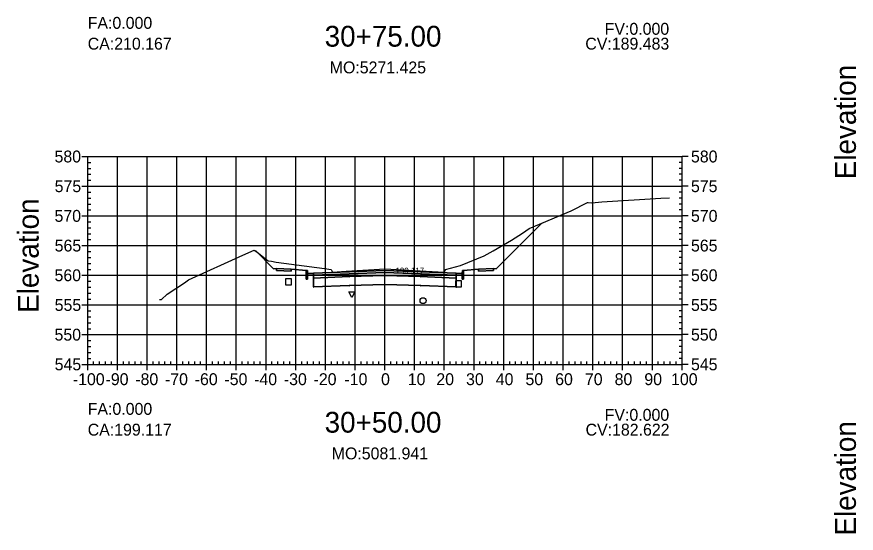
# Model space of a CAD drawing. Extents: x 704834 to 709892, y 372981 to 377533.
# Drawn here: x 706563 to 706845.5, y 373505.9 to 373679.9 of the extents above; entities that cross this region are included whole.
import ezdxf

# ---------------------------------------------------------------- set-up
doc = ezdxf.new("R2010")
doc.units = 0
for name, color, linetype in [('1', 7, 'Continuous'), ('10', 7, 'Continuous'), ('13', 7, 'Continuous'), ('14', 7, 'Continuous'), ('4', 7, 'Continuous'), ('57', 7, 'Continuous'), ('59', 7, 'Continuous'), ('60', 7, 'Continuous'), ('Default_Xsect', 7, 'Continuous'), ('Existing', 7, 'Continuous')]:
    doc.layers.add(name, color=color, linetype=linetype)

msp = doc.modelspace()

# ---------------------------------------------------------------- linework, layer by layer
for points in [[(706724.37, 373595.02), (706739.69, 373610.34)], [(706649.37, 373595.02), (706643.5, 373600.89)], [(706650.37, 373595.06), (706649.37, 373595.02)], [(706660.37, 373594.46), (706655.37, 373594.86)], [(706713.37, 373594.46), (706718.37, 373594.86)], [(706723.37, 373595.06), (706724.37, 373595.02)]]:
    msp.add_lwpolyline(points)
for points in [[(706655.37, 373594.86), (706650.37, 373595.06), (706650.37, 373594.4), (706655.37, 373594.2)], [(706718.37, 373594.2), (706723.37, 373594.4), (706723.37, 373595.06), (706718.37, 373594.86)], [(706660.87, 373593.46), (706660.79, 373594.46), (706660.37, 373594.46), (706660.37, 373591.46), (706660.87, 373591.46)], [(706662.87, 373593.54), (706660.87, 373593.46), (706660.87, 373592.8), (706662.87, 373592.88)], [(706662.82, 373591.83), (706662.92, 373591.83), (706662.92, 373591.93), (706662.82, 373591.93)], [(706686.87, 373593.72), (706698.87, 373593.36), (706710.87, 373592.88), (706710.87, 373593.54), (706698.87, 373594.02), (706686.87, 373594.38), (706674.87, 373594.02), (706662.87, 373593.54), (706662.87, 373592.88), (706674.87, 373593.36)], [(706686.87, 373592.72), (706698.87, 373592.36), (706710.87, 373591.88), (706710.87, 373592.88), (706698.87, 373593.36), (706686.87, 373593.72), (706674.87, 373593.36), (706662.87, 373592.88), (706662.87, 373591.88), (706674.87, 373592.36)], [(706686.87, 373589.72), (706698.87, 373589.36), (706710.87, 373588.88), (706710.87, 373591.88), (706698.87, 373592.36), (706686.87, 373592.72), (706674.87, 373592.36), (706662.87, 373591.88), (706662.87, 373588.88), (706674.87, 373589.36)], [(706674.82, 373592.31), (706674.92, 373592.31), (706674.92, 373592.41), (706674.82, 373592.41)], [(706686.82, 373593.67), (706686.92, 373593.67), (706686.92, 373593.77), (706686.82, 373593.77)], [(706686.82, 373592.67), (706686.92, 373592.67), (706686.92, 373592.77), (706686.82, 373592.77)], [(706698.82, 373592.31), (706698.92, 373592.31), (706698.92, 373592.41), (706698.82, 373592.41)], [(706710.82, 373591.83), (706710.92, 373591.83), (706710.92, 373591.93), (706710.82, 373591.93)], [(706710.87, 373592.88), (706712.87, 373592.8), (706712.87, 373593.46), (706710.87, 373593.54)], [(706712.87, 373591.46), (706713.37, 373591.46), (706713.37, 373594.46), (706712.96, 373594.46), (706712.87, 373593.46)], [(706674.82, 373589.31), (706674.92, 373589.31), (706674.92, 373589.41), (706674.82, 373589.41)], [(706686.82, 373589.67), (706686.92, 373589.67), (706686.92, 373589.77), (706686.82, 373589.77)], [(706698.82, 373589.31), (706698.92, 373589.31), (706698.92, 373589.41), (706698.82, 373589.41)], [(706662.82, 373588.83), (706662.92, 373588.83), (706662.92, 373588.93), (706662.82, 373588.93)], [(706710.82, 373588.83), (706710.92, 373588.83), (706710.92, 373588.93), (706710.82, 373588.93)]]:
    msp.add_lwpolyline(points, close=True)
at = {"layer": '1'}
for points in [[(706643.5, 373600.89), (706643.76, 373600.76), (706645.58, 373599.2), (706647.55, 373597.73), (706648.71, 373597.62), (706650.28, 373597.18), (706666.5, 373595.07), (706668.76, 373594.73), (706669.02, 373594.32), (706669.25, 373593.86), (706673.84, 373594.17), (706687.01, 373594.99), (706690.78, 373594.8), (706706.8, 373593.85), (706707.01, 373594.18), (706707.32, 373594.78), (706710.62, 373595.66), (706712.3, 373596.12), (706720.32, 373599.37), (706723.31, 373601), (706729.47, 373604.61), (706733.14, 373606.99), (706735.39, 373608.52), (706739.69, 373610.34), (706724.37, 373595.02), (706723.37, 373595.06), (706723.37, 373594.4), (706718.37, 373594.2), (706718.37, 373594.86), (706713.37, 373594.46), (706713.37, 373591.46), (706712.87, 373591.46), (706712.87, 373592.8), (706710.87, 373592.88), (706710.87, 373591.88), (706710.87, 373588.88), (706698.87, 373589.36), (706686.87, 373589.72), (706674.87, 373589.36), (706662.87, 373588.88), (706662.87, 373591.88), (706662.87, 373592.88), (706660.87, 373592.8), (706660.87, 373591.46), (706660.37, 373591.46), (706660.37, 373594.46), (706655.37, 373594.86), (706655.37, 373594.2), (706650.37, 373594.4), (706650.37, 373595.06), (706649.37, 373595.02)], [(706675.75, 373585.29), (706674.75, 373587.29), (706676.75, 373587.29)]]:
    msp.add_lwpolyline(points, close=True, dxfattribs=at)
at = {"layer": '10'}
msp.add_lwpolyline([(706653.41, 373589.64), (706655.41, 373589.64), (706655.41, 373591.64), (706653.41, 373591.64)], close=True, dxfattribs=at)
at = {"layer": '13'}
msp.add_circle((706699.71, 373584.27), 1, dxfattribs=at)
at = {"layer": '14'}
for points in [[(706739.69, 373610.34), (706739.69, 373610.39), (706739.69, 373610.34), (706739.64, 373610.34), (706739.69, 373610.34), (706739.69, 373610.29), (706739.69, 373610.34), (706739.74, 373610.34)], [(706643.5, 373600.89), (706643.5, 373600.94), (706643.5, 373600.89), (706643.45, 373600.89), (706643.5, 373600.89), (706643.5, 373600.84), (706643.5, 373600.89), (706643.55, 373600.89)], [(706662.87, 373593.54), (706662.87, 373593.59), (706662.87, 373593.54), (706662.82, 373593.54), (706662.87, 373593.54), (706662.87, 373593.49), (706662.87, 373593.54), (706662.92, 373593.54)], [(706674.87, 373594.02), (706674.87, 373594.07), (706674.87, 373594.02), (706674.82, 373594.02), (706674.87, 373594.02), (706674.87, 373593.97), (706674.87, 373594.02), (706674.92, 373594.02)], [(706686.87, 373594.38), (706686.87, 373594.43), (706686.87, 373594.38), (706686.82, 373594.38), (706686.87, 373594.38), (706686.87, 373594.33), (706686.87, 373594.38), (706686.92, 373594.38)], [(706698.87, 373594.02), (706698.87, 373594.07), (706698.87, 373594.02), (706698.82, 373594.02), (706698.87, 373594.02), (706698.87, 373593.97), (706698.87, 373594.02), (706698.92, 373594.02)], [(706710.87, 373593.54), (706710.87, 373593.59), (706710.87, 373593.54), (706710.82, 373593.54), (706710.87, 373593.54), (706710.87, 373593.49), (706710.87, 373593.54), (706710.92, 373593.54)]]:
    msp.add_lwpolyline(points, dxfattribs=at)
at = {"layer": '4'}
msp.add_lwpolyline([(706710.64, 373588.94), (706712.64, 373588.94), (706712.64, 373590.94), (706710.64, 373590.94)], close=True, dxfattribs=at)
at = {"layer": '57'}
for p, q in [((706584.87, 373632.82), (706586.87, 373632.82)), ((706586.87, 373632.82), (706786.87, 373632.82)), ((706586.87, 373562.82), (706586.87, 373632.82)), ((706586.87, 373562.82), (706586.87, 373632.82)), ((706596.87, 373562.82), (706596.87, 373632.82)), ((706606.87, 373562.82), (706606.87, 373632.82)), ((706616.87, 373562.82), (706616.87, 373632.82)), ((706626.87, 373562.82), (706626.87, 373632.82)), ((706636.87, 373562.82), (706636.87, 373632.82)), ((706646.87, 373562.82), (706646.87, 373632.82)), ((706656.87, 373562.82), (706656.87, 373632.82)), ((706666.87, 373562.82), (706666.87, 373632.82)), ((706676.87, 373562.82), (706676.87, 373632.82)), ((706686.87, 373562.82), (706686.87, 373632.82)), ((706696.87, 373562.82), (706696.87, 373632.82)), ((706706.87, 373562.82), (706706.87, 373632.82)), ((706716.87, 373562.82), (706716.87, 373632.82)), ((706726.87, 373562.82), (706726.87, 373632.82)), ((706736.87, 373562.82), (706736.87, 373632.82)), ((706746.87, 373562.82), (706746.87, 373632.82)), ((706756.87, 373562.82), (706756.87, 373632.82)), ((706766.87, 373562.82), (706766.87, 373632.82)), ((706776.87, 373562.82), (706776.87, 373632.82)), ((706786.87, 373562.82), (706786.87, 373632.82)), ((706786.87, 373562.82), (706786.87, 373632.82)), ((706788.87, 373632.82), (706786.87, 373632.82)), ((706586.87, 373630.82), (706587.87, 373630.82)), ((706586.87, 373628.82), (706587.87, 373628.82)), ((706786.87, 373630.82), (706785.87, 373630.82)), ((706786.87, 373628.82), (706785.87, 373628.82)), ((706586.87, 373626.82), (706587.87, 373626.82)), ((706786.87, 373626.82), (706785.87, 373626.82)), ((706586.87, 373624.82), (706587.87, 373624.82)), ((706786.87, 373624.82), (706785.87, 373624.82)), ((706584.87, 373622.82), (706586.87, 373622.82)), ((706586.87, 373622.82), (706786.87, 373622.82)), ((706586.87, 373620.82), (706587.87, 373620.82)), ((706786.87, 373620.82), (706785.87, 373620.82)), ((706788.87, 373622.82), (706786.87, 373622.82)), ((706586.87, 373618.82), (706587.87, 373618.82)), ((706786.87, 373618.82), (706785.87, 373618.82)), ((706586.87, 373616.82), (706587.87, 373616.82)), ((706586.87, 373614.82), (706587.87, 373614.82)), ((706786.87, 373616.82), (706785.87, 373616.82)), ((706786.87, 373614.82), (706785.87, 373614.82)), ((706584.87, 373612.82), (706586.87, 373612.82)), ((706586.87, 373612.82), (706786.87, 373612.82)), ((706788.87, 373612.82), (706786.87, 373612.82)), ((706586.87, 373610.82), (706587.87, 373610.82)), ((706586.87, 373608.82), (706587.87, 373608.82)), ((706786.87, 373610.82), (706785.87, 373610.82)), ((706786.87, 373608.82), (706785.87, 373608.82)), ((706586.87, 373606.82), (706587.87, 373606.82)), ((706786.87, 373606.82), (706785.87, 373606.82)), ((706586.87, 373604.82), (706587.87, 373604.82)), ((706786.87, 373604.82), (706785.87, 373604.82)), ((706584.87, 373602.82), (706586.87, 373602.82)), ((706586.87, 373602.82), (706786.87, 373602.82)), ((706586.87, 373600.82), (706587.87, 373600.82)), ((706786.87, 373600.82), (706785.87, 373600.82)), ((706788.87, 373602.82), (706786.87, 373602.82)), ((706586.87, 373598.82), (706587.87, 373598.82)), ((706786.87, 373598.82), (706785.87, 373598.82)), ((706586.87, 373596.82), (706587.87, 373596.82)), ((706586.87, 373594.82), (706587.87, 373594.82)), ((706786.87, 373596.82), (706785.87, 373596.82)), ((706786.87, 373594.82), (706785.87, 373594.82)), ((706584.87, 373592.82), (706586.87, 373592.82)), ((706586.87, 373592.82), (706786.87, 373592.82)), ((706788.87, 373592.82), (706786.87, 373592.82)), ((706586.87, 373590.82), (706587.87, 373590.82)), ((706786.87, 373590.82), (706785.87, 373590.82)), ((706586.87, 373588.82), (706587.87, 373588.82)), ((706586.87, 373586.82), (706587.87, 373586.82)), ((706786.87, 373588.82), (706785.87, 373588.82)), ((706786.87, 373586.82), (706785.87, 373586.82)), ((706586.87, 373584.82), (706587.87, 373584.82)), ((706786.87, 373584.82), (706785.87, 373584.82)), ((706584.87, 373582.82), (706586.87, 373582.82)), ((706586.87, 373582.82), (706786.87, 373582.82)), ((706586.87, 373580.82), (706587.87, 373580.82)), ((706786.87, 373580.82), (706785.87, 373580.82)), ((706788.87, 373582.82), (706786.87, 373582.82)), ((706586.87, 373578.82), (706587.87, 373578.82)), ((706786.87, 373578.82), (706785.87, 373578.82)), ((706586.87, 373576.82), (706587.87, 373576.82)), ((706786.87, 373576.82), (706785.87, 373576.82)), ((706584.87, 373572.82), (706586.87, 373572.82)), ((706586.87, 373574.82), (706587.87, 373574.82)), ((706586.87, 373572.82), (706786.87, 373572.82)), ((706786.87, 373574.82), (706785.87, 373574.82)), ((706788.87, 373572.82), (706786.87, 373572.82)), ((706586.87, 373570.82), (706587.87, 373570.82)), ((706786.87, 373570.82), (706785.87, 373570.82)), ((706586.87, 373568.82), (706587.87, 373568.82)), ((706586.87, 373566.82), (706587.87, 373566.82)), ((706786.87, 373568.82), (706785.87, 373568.82)), ((706786.87, 373566.82), (706785.87, 373566.82)), ((706586.87, 373564.82), (706587.87, 373564.82)), ((706588.87, 373562.82), (706588.87, 373563.82)), ((706590.87, 373562.82), (706590.87, 373563.82)), ((706592.87, 373562.82), (706592.87, 373563.82)), ((706594.87, 373562.82), (706594.87, 373563.82)), ((706598.87, 373562.82), (706598.87, 373563.82)), ((706600.87, 373562.82), (706600.87, 373563.82)), ((706602.87, 373562.82), (706602.87, 373563.82)), ((706604.87, 373562.82), (706604.87, 373563.82)), ((706608.87, 373562.82), (706608.87, 373563.82)), ((706610.87, 373562.82), (706610.87, 373563.82)), ((706612.87, 373562.82), (706612.87, 373563.82)), ((706614.87, 373562.82), (706614.87, 373563.82)), ((706618.87, 373562.82), (706618.87, 373563.82)), ((706620.87, 373562.82), (706620.87, 373563.82)), ((706622.87, 373562.82), (706622.87, 373563.82)), ((706624.87, 373562.82), (706624.87, 373563.82)), ((706628.87, 373562.82), (706628.87, 373563.82)), ((706630.87, 373562.82), (706630.87, 373563.82)), ((706632.87, 373562.82), (706632.87, 373563.82)), ((706634.87, 373562.82), (706634.87, 373563.82)), ((706638.87, 373562.82), (706638.87, 373563.82)), ((706640.87, 373562.82), (706640.87, 373563.82)), ((706642.87, 373562.82), (706642.87, 373563.82)), ((706644.87, 373562.82), (706644.87, 373563.82)), ((706648.87, 373562.82), (706648.87, 373563.82)), ((706650.87, 373562.82), (706650.87, 373563.82)), ((706652.87, 373562.82), (706652.87, 373563.82)), ((706654.87, 373562.82), (706654.87, 373563.82)), ((706658.87, 373562.82), (706658.87, 373563.82)), ((706660.87, 373562.82), (706660.87, 373563.82)), ((706662.87, 373562.82), (706662.87, 373563.82)), ((706664.87, 373562.82), (706664.87, 373563.82)), ((706668.87, 373562.82), (706668.87, 373563.82)), ((706670.87, 373562.82), (706670.87, 373563.82)), ((706672.87, 373562.82), (706672.87, 373563.82)), ((706674.87, 373562.82), (706674.87, 373563.82)), ((706678.87, 373562.82), (706678.87, 373563.82)), ((706680.87, 373562.82), (706680.87, 373563.82)), ((706682.87, 373562.82), (706682.87, 373563.82)), ((706684.87, 373562.82), (706684.87, 373563.82)), ((706688.87, 373562.82), (706688.87, 373563.82)), ((706690.87, 373562.82), (706690.87, 373563.82)), ((706692.87, 373562.82), (706692.87, 373563.82)), ((706694.87, 373562.82), (706694.87, 373563.82)), ((706698.87, 373562.82), (706698.87, 373563.82)), ((706700.87, 373562.82), (706700.87, 373563.82)), ((706702.87, 373562.82), (706702.87, 373563.82)), ((706704.87, 373562.82), (706704.87, 373563.82)), ((706708.87, 373562.82), (706708.87, 373563.82)), ((706710.87, 373562.82), (706710.87, 373563.82)), ((706712.87, 373562.82), (706712.87, 373563.82)), ((706714.87, 373562.82), (706714.87, 373563.82)), ((706718.87, 373562.82), (706718.87, 373563.82)), ((706720.87, 373562.82), (706720.87, 373563.82)), ((706722.87, 373562.82), (706722.87, 373563.82)), ((706724.87, 373562.82), (706724.87, 373563.82)), ((706728.87, 373562.82), (706728.87, 373563.82)), ((706730.87, 373562.82), (706730.87, 373563.82)), ((706732.87, 373562.82), (706732.87, 373563.82)), ((706734.87, 373562.82), (706734.87, 373563.82)), ((706738.87, 373562.82), (706738.87, 373563.82)), ((706740.87, 373562.82), (706740.87, 373563.82)), ((706742.87, 373562.82), (706742.87, 373563.82)), ((706744.87, 373562.82), (706744.87, 373563.82)), ((706748.87, 373562.82), (706748.87, 373563.82)), ((706750.87, 373562.82), (706750.87, 373563.82)), ((706752.87, 373562.82), (706752.87, 373563.82)), ((706754.87, 373562.82), (706754.87, 373563.82)), ((706758.87, 373562.82), (706758.87, 373563.82)), ((706760.87, 373562.82), (706760.87, 373563.82)), ((706762.87, 373562.82), (706762.87, 373563.82)), ((706764.87, 373562.82), (706764.87, 373563.82)), ((706768.87, 373562.82), (706768.87, 373563.82)), ((706770.87, 373562.82), (706770.87, 373563.82)), ((706772.87, 373562.82), (706772.87, 373563.82)), ((706774.87, 373562.82), (706774.87, 373563.82)), ((706778.87, 373562.82), (706778.87, 373563.82)), ((706780.87, 373562.82), (706780.87, 373563.82)), ((706782.87, 373562.82), (706782.87, 373563.82)), ((706784.87, 373562.82), (706784.87, 373563.82)), ((706786.87, 373564.82), (706785.87, 373564.82)), ((706584.87, 373562.82), (706586.87, 373562.82)), ((706586.87, 373562.82), (706786.87, 373562.82)), ((706586.87, 373562.82), (706786.87, 373562.82)), ((706586.87, 373560.82), (706586.87, 373562.82)), ((706596.87, 373560.82), (706596.87, 373562.82)), ((706606.87, 373560.82), (706606.87, 373562.82)), ((706616.87, 373560.82), (706616.87, 373562.82)), ((706626.87, 373560.82), (706626.87, 373562.82)), ((706636.87, 373560.82), (706636.87, 373562.82)), ((706646.87, 373560.82), (706646.87, 373562.82)), ((706656.87, 373560.82), (706656.87, 373562.82)), ((706666.87, 373560.82), (706666.87, 373562.82)), ((706676.87, 373560.82), (706676.87, 373562.82)), ((706686.87, 373560.82), (706686.87, 373562.82)), ((706696.87, 373560.82), (706696.87, 373562.82)), ((706706.87, 373560.82), (706706.87, 373562.82)), ((706716.87, 373560.82), (706716.87, 373562.82)), ((706726.87, 373560.82), (706726.87, 373562.82)), ((706736.87, 373560.82), (706736.87, 373562.82)), ((706746.87, 373560.82), (706746.87, 373562.82)), ((706756.87, 373560.82), (706756.87, 373562.82)), ((706766.87, 373560.82), (706766.87, 373562.82)), ((706776.87, 373560.82), (706776.87, 373562.82)), ((706786.87, 373560.82), (706786.87, 373562.82)), ((706788.87, 373562.82), (706786.87, 373562.82))]:
    msp.add_line(p, q, dxfattribs=at)
at = {"layer": 'Default_Xsect'}
msp.add_lwpolyline([(706643.5, 373600.89), (706649.37, 373595.02), (706650.37, 373595.06), (706655.37, 373594.86), (706660.37, 373594.46), (706660.79, 373594.46), (706660.87, 373593.46), (706662.87, 373593.54), (706674.87, 373594.02), (706686.87, 373594.38), (706698.87, 373594.02), (706710.87, 373593.54), (706712.87, 373593.46), (706712.96, 373594.46), (706713.37, 373594.46), (706718.37, 373594.86), (706723.37, 373595.06), (706724.37, 373595.02), (706739.69, 373610.34)], dxfattribs=at)
at = {"layer": 'Existing'}
msp.add_lwpolyline([(706611.01, 373584.68), (706611.73, 373584.63), (706613.61, 373586.44), (706619.44, 373590.27), (706620.81, 373591.28), (706639.02, 373599.6), (706642.88, 373601.23), (706643.76, 373600.76), (706645.58, 373599.2), (706647.55, 373597.73), (706648.71, 373597.62), (706650.28, 373597.18), (706666.5, 373595.07), (706668.76, 373594.73), (706669.02, 373594.32), (706669.25, 373593.86), (706673.84, 373594.17), (706687.01, 373594.99), (706690.78, 373594.8), (706706.8, 373593.85), (706707.01, 373594.18), (706707.32, 373594.78), (706710.62, 373595.66), (706712.3, 373596.12), (706720.32, 373599.37), (706723.31, 373601), (706729.47, 373604.61), (706733.14, 373606.99), (706735.39, 373608.52), (706749.58, 373614.53), (706755.02, 373617.32), (706755.23, 373617.32), (706756.47, 373617.26), (706759.87, 373617.51), (706779.7, 373618.77), (706782.64, 373618.93)], dxfattribs=at)

# ---------------------------------------------------------------- texts
for s, p in [('CA:210.167', (706586.87, 373668.82)), ('CV:189.483', (706754.31, 373668.82)), ('CA:199.117', (706586.87, 373538.82)), ('CV:182.622', (706754.4, 373538.82))]:
    msp.add_text(s, height=4).set_placement(p)
at = {"layer": '1'}
for s, p in [('30+75.00', (706666.6, 373669.82)), ('30+50.00', (706666.6, 373539.82))]:
    msp.add_text(s, height=7, dxfattribs=at).set_placement(p)
at = {"layer": '14'}
for p in [(706650.34, 373595.01), (706723.34, 373595.01), (706650.34, 373594.35), (706655.34, 373594.15), (706718.34, 373594.15), (706723.34, 373594.35)]:
    msp.add_text('+', height=0.1, dxfattribs=at).set_placement(p)
at = {"layer": '57'}
for s, p in [('580', (706575.7, 373630.82)), ('580', (706789.87, 373630.82)), ('575', (706575.75, 373620.82)), ('575', (706789.87, 373620.82)), ('570', (706575.7, 373610.82)), ('570', (706789.87, 373610.82)), ('565', (706575.75, 373600.82)), ('565', (706789.87, 373600.82)), ('560', (706575.7, 373590.82)), ('560', (706789.87, 373590.82)), ('555', (706575.75, 373580.82)), ('555', (706789.87, 373580.82)), ('550', (706575.7, 373570.82)), ('550', (706789.87, 373570.82)), ('545', (706575.75, 373560.82)), ('545', (706789.87, 373560.82)), ('-100', (706581.86, 373555.82)), ('-90', (706592.87, 373555.82)), ('-80', (706602.87, 373555.82)), ('-70', (706612.87, 373555.82)), ('-60', (706622.87, 373555.82)), ('-50', (706632.87, 373555.82)), ('-40', (706642.87, 373555.82)), ('-30', (706652.87, 373555.82)), ('-20', (706662.87, 373555.82)), ('-10', (706673.26, 373555.82)), ('0', (706685.58, 373555.82)), ('10', (706694.57, 373555.82)), ('20', (706704.18, 373555.82)), ('30', (706714.18, 373555.82)), ('40', (706724.18, 373555.82)), ('50', (706734.18, 373555.82)), ('60', (706744.18, 373555.82)), ('70', (706754.18, 373555.82)), ('80', (706764.18, 373555.82)), ('90', (706774.18, 373555.82)), ('100', (706783.17, 373555.82))]:
    msp.add_text(s, height=4, dxfattribs=at).set_placement(p)
at = {"layer": '59'}
for s, height, p in [('FA:0.000', 4, (706586.87, 373675.82)), ('FV:0.000', 4, (706760.83, 373673.82)), ('MO:5271.425', 4, (706668.31, 373660.82)), ('199.117', 2, (706690.43, 373593.38)), ('FA:0.000', 4, (706586.87, 373545.82)), ('FV:0.000', 4, (706760.83, 373543.82)), ('MO:5081.941', 4, (706668.99, 373530.82))]:
    msp.add_text(s, height=height, dxfattribs=at).set_placement(p)
at = {"layer": '60'}
for p in [(706845.37, 373625.18), (706570.37, 373580.18), (706845.37, 373505.18)]:
    msp.add_text('Elevation', height=7, rotation=90, dxfattribs=at).set_placement(p)

doc.saveas('drawing.dxf')
